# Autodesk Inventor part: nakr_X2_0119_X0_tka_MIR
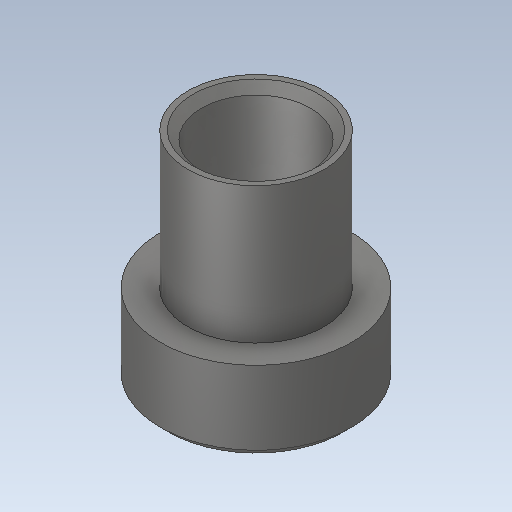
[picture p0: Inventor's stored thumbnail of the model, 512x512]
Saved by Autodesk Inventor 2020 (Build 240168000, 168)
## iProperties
Created: 2015-11
Part Number: nakr_X2_0119_X0_tka_MIR
Material: Ogólny
Document SubType Name: Modeling
Designer: Tomasz
Density: 1 g/cm^3
Appearance: Domyślna
Sending System: SolidWorks 2017
Last Author: Tomasz
Last Saved: 2017-10-01
Author: Tomasz
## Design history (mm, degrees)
feature "Imported1"
node "Bryła1"
